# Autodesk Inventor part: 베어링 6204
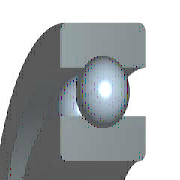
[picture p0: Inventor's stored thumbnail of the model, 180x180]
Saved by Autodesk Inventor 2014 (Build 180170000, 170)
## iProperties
IsCustomPart: 0
Created: 2015-12
Part Number: 베어링 6204
Material: 강철, 연강
Description: 깊은 그루브 볼 베어링
Document SubType Name: Modeling
Standard: KS B 2023
Designer: mdu
Standards Organization: KS
Language: ko-KR
Size Designation: 6204 - 20 x 47 x 14
Categories: <MemberInstance><Categories><Category DisplayName="샤프트 부품" InternalName="7f7aeb1f-a693-4053-b835-cee3144e0d98" Mnemonic="SHFT"><Category DisplayName="베어링" Inter
Density: 7.86 g/cm^3
Mass: 104.255 g
Surface Area: 87.8912 cm^2
Volume: 13.264 cm^3
Appearance: Steel
Author: mud
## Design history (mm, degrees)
sketch "스케치" dims "d0" = 7.02 (= -0.26 x WD + 0.26 x BD)
  geometry: L1 (3.49, 16.75)-(10.51, 16.75); L2 (7, 16.75)-(7, 13.24); L3 (7, 16.75)-(7, 20.26); L4 (4.392, 14.401)-(0, 14.401); L5 (0, 10)-(14, 10); L6 (4.392, 19.099)-(0, 19.099); L7 (0, 23.5)-(14, 23.5); L8 (14, 10)-(14, 14.401); L9 (9.608, 14.401)-(14, 14.401); L10 (9.608, 19.099)-(14, 19.099); L11 (14, 23.5)-(14, 19.099); L12 (-1.4, 0)-(8.4, 0) reference; L13 (0, -0.3)-(0, 5.3) reference
  constraints: 22 end point, 4 point on line, 2 collinear, 2 perpendicular, 2 symmetric about line, 1 midpoint, 1 parallel, 14 other
  dimensions: "d9" = 20 diameter of L5 L12 (= WD); "d11" = 47 diameter of L7 L12 (= BD); "d12" = 14 distance between parallel lines of L8 L13 (= KB); "d13" = 28.802 diameter of L9 L12 (= 0.326 x BD + 0.674 x WD)
revolve "본체" stored, may be unused: angle "d6" = 90 deg
revolve "볼" stored, may be unused: angle "d7" = 90 deg
pattern_circular "IDS_ARRAYBALL[SIMPL:T]" dims angle "d3" = 360 deg
body "Solid1"
fillet "모깎기1" dims "d1" = 1 (= KRS)
other parameters: "WD" = 20 [user parameter; used in 5 equation terms], "BD" = 47 [user parameter; used in 5 equation terms], "KB" = 14 [user parameter; used in 1 equation term], "KRS" = 1 [user parameter; used in 1 equation term], "d4" = 0, "d5" = 0, "d8" = 0, "d14" = 0, "d15" = 0, "BBA" = 0 [user parameter], "BC0" = 6550000 [user parameter], "BC" = 1.27e+07 [user parameter], "BR" = 23.5 (= 0.5 x BD) [user parameter]
